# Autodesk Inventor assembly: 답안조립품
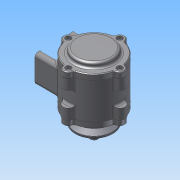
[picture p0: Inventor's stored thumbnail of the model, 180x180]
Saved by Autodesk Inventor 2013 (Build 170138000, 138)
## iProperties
Created: 2015-03
Part Number: 답안조립품
Document SubType Name: Assembly
Designer: ST3
Author: ST3
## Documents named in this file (9)
- C:\Users\ST3\Desktop\450305V1042\답안조립품.iam
- C:\Users\ST3\Desktop\450305V1042\1-본체.ipt
- C:\Users\ST3\Desktop\450305V1042\축.ipt
- C:\Users\ST3\Desktop\450305V1042\V벨트풀리.ipt
- C:\Users\ST3\Desktop\450305V1042\커버.ipt
- C:\Users\ST3\Desktop\450305V1042\베어링 6204.ipt
- C:\Users\ST3\Desktop\450305V1042\오일실.ipt
- C:\Users\ST3\Desktop\450305V1042\커버2.ipt
- C:\Users\ST3\Desktop\450305V1042\키(4 x 4 x 12).ipt
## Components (6 placed, 5 different names)
1. 1-본체:1
2. 그루브 풀리1:1
3. KS B 2023 6204 - 20 x 47 x 14:1
4. KS B 2023 6204 - 20 x 47 x 14:2
5. KS B 2804 D D - 20 32 8:1
6. KS B 1311 (I) 4 x 4 x 12:1
